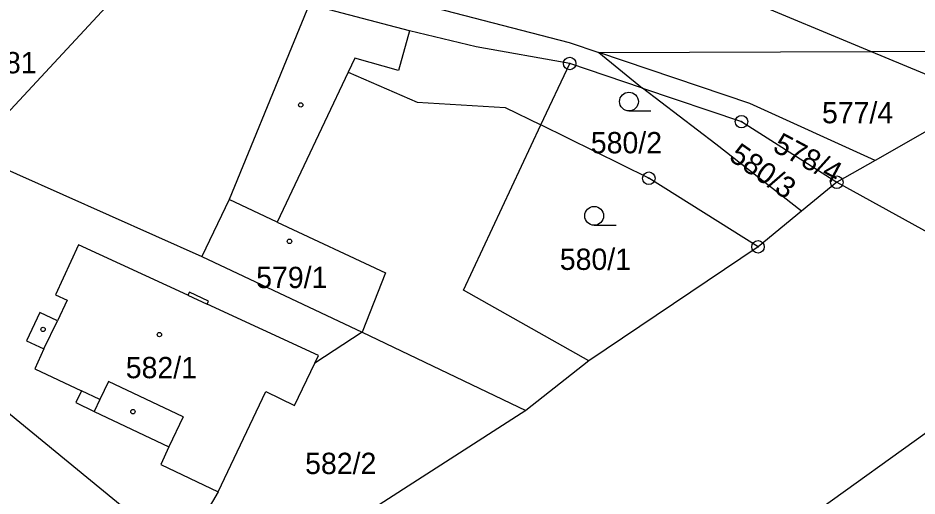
# Model space of a CAD drawing. Extents: x -776606 to -776076, y -974328 to -973875.
# Drawn here: x -776421.1 to -776349.3, y -974258.8 to -974220.6 of the extents above; entities that cross this region are included whole.
import ezdxf

# ---------------------------------------------------------------- set-up
doc = ezdxf.new("R2010")
doc.units = 0
for name, color, linetype in [('Hranice parcel', 7, 'Continuous'), ('Parcelní čísla', 7, 'Continuous'), ('Poz předměty', 7, 'Continuous'), ('Vnitřní kresba', 7, 'Continuous'), ('Značky bodu BP', 7, 'Continuous'), ('Značky budov', 7, 'Continuous'), ('Značky kultur', 7, 'Continuous')]:
    doc.layers.add(name, color=color, linetype=linetype)

msp = doc.modelspace()

# ---------------------------------------------------------------- linework, layer by layer
at = {"layer": 'Hranice parcel'}
for p, q in [((-776374.7, -974223.37), (-776371.21, -974226.22)), ((-776379.34, -974229.15), (-776377.04, -974224.25)), ((-776371.21, -974226.22), (-776377.04, -974224.25)), ((-776370.72, -974233.41), (-776379.34, -974229.15)), ((-776352.62, -974231.99), (-776355.69, -974233.73)), ((-776361.99, -974238.89), (-776370.72, -974233.41)), ((-776355.69, -974233.73), (-776358.51, -974236.04)), ((-776358.51, -974236.04), (-776361.99, -974238.89)), ((-776361.99, -974238.89), (-776375.51, -974247.99)), ((-776406.44, -974239.65), (-776393.62, -974245.71)), ((-776432.18, -974243.72), (-776408.09, -974263.43)), ((-776393.62, -974245.71), (-776397.41, -974248.18)), ((-776393.62, -974245.71), (-776380.54, -974251.96)), ((-776375.51, -974247.99), (-776380.54, -974251.96)), ((-776380.54, -974251.96), (-776403.84, -974266.91)), ((-776405.12, -974258.44), (-776408.09, -974263.43))]:
    msp.add_line(p, q, dxfattribs=at)
for points in [[(-776396.96, -974217.4), (-776377.08, -974222.57), (-776374.7, -974223.37)], [(-776397.85, -974219.54), (-776399.26, -974222.98), (-776404.25, -974235.1), (-776406.44, -974239.65)], [(-776377.04, -974224.25), (-776384.52, -974222.93), (-776389.85, -974221.65), (-776397.85, -974219.54)], [(-776374.7, -974223.37), (-776352.96, -974223.29), (-776340.63, -974223.24)], [(-776352.62, -974231.99), (-776362.64, -974227.45), (-776374.7, -974223.37)], [(-776340.63, -974223.24), (-776343.95, -974227.05), (-776352.62, -974231.99)], [(-776371.21, -974226.22), (-776363.31, -974228.89), (-776355.69, -974233.73)], [(-776358.51, -974236.04), (-776365.36, -974230.68), (-776371.21, -974226.22)], [(-776430.93, -974228.6), (-776424.97, -974231.42), (-776406.44, -974239.65)], [(-776375.51, -974247.99), (-776385.52, -974242.34), (-776379.34, -974229.15)], [(-776397.41, -974248.18), (-776397.12, -974247.56), (-776406, -974243.47), (-776405.89, -974243.22), (-776407.43, -974242.51), (-776407.54, -974242.75), (-776416.28, -974238.73), (-776418.12, -974242.71), (-776417.19, -974243.14), (-776417.97, -974244.8), (-776419.38, -974244.14), (-776420.43, -974246.39), (-776419.05, -974247.04), (-776419.78, -974248.62), (-776416.06, -974250.39), (-776416.51, -974251.32), (-776415.03, -974252.03), (-776409.06, -974254.87), (-776409.72, -974256.26), (-776405.12, -974258.44)], [(-776405.12, -974258.44), (-776401.32, -974250.45), (-776399.02, -974251.55), (-776397.41, -974248.18)]]:
    msp.add_lwpolyline(points, dxfattribs=at)
at = {"layer": 'Poz předměty'}
msp.add_line((-776358.8, -974261.05), (-776342.73, -974249.52), dxfattribs=at)
at = {"layer": 'Vnitřní kresba'}
for p, q in [((-776372.39, -974215.17), (-776352.96, -974223.29)), ((-776424.97, -974231.42), (-776410.75, -974216.12)), ((-776389.85, -974221.65), (-776390.73, -974224.8)), ((-776394.22, -974223.82), (-776394.74, -974224.93)), ((-776390.73, -974224.8), (-776394.22, -974223.82)), ((-776352.96, -974223.29), (-776343.95, -974227.05)), ((-776394.74, -974224.93), (-776400.42, -974236.93)), ((-776394.74, -974224.93), (-776389.22, -974227.33)), ((-776389.22, -974227.33), (-776382.19, -974227.77)), ((-776382.19, -974227.77), (-776379.34, -974229.15)), ((-776355.69, -974233.73), (-776345.5, -974239.35)), ((-776400.42, -974236.93), (-776404.25, -974235.1)), ((-776400.42, -974236.93), (-776391.77, -974240.97)), ((-776391.77, -974240.97), (-776393.62, -974245.71)), ((-776407.54, -974242.75), (-776406, -974243.47)), ((-776419.05, -974247.04), (-776417.97, -974244.8)), ((-776413.9, -974249.65), (-776414.58, -974251.09)), ((-776407.93, -974252.47), (-776413.9, -974249.65)), ((-776414.58, -974251.09), (-776416.06, -974250.39)), ((-776414.58, -974251.09), (-776415.03, -974252.03)), ((-776407.93, -974252.47), (-776409.06, -974254.87))]:
    msp.add_line(p, q, dxfattribs=at)
at = {"layer": 'Značky bodu BP'}
for centre, radius in [((-776377.04, -974224.25), 0.5), ((-776377.04, -974224.25), 0.0303), ((-776363.31, -974228.89), 0.5), ((-776363.31, -974228.89), 0.0303), ((-776370.72, -974233.41), 0.5), ((-776370.72, -974233.41), 0.0303), ((-776355.69, -974233.73), 0.5), ((-776355.69, -974233.73), 0.0303), ((-776361.99, -974238.89), 0.5), ((-776361.99, -974238.89), 0.0303)]:
    msp.add_circle(centre, radius, dxfattribs=at)
at = {"layer": 'Značky budov'}
for centre in [(-776398.527, -974227.559), (-776399.427, -974238.449), (-776419.117, -974245.479), (-776409.827, -974245.899), (-776411.937, -974252.049)]:
    msp.add_circle(centre, 0.175, dxfattribs=at)
at = {"layer": 'Značky kultur'}
for p, q in [((-776372.303, -974228.04), (-776370.553, -974228.04)), ((-776375.083, -974237.16), (-776373.333, -974237.16))]:
    msp.add_line(p, q, dxfattribs=at)
for centre in [(-776372.303, -974227.29), (-776375.083, -974236.41)]:
    msp.add_circle(centre, 0.75, dxfattribs=at)

# ---------------------------------------------------------------- texts
at = {"layer": 'Parcelní čísla'}
for s, p in [('581', (-776423.43, -974225.03)), ('577/4', (-776356.88, -974229.02)), ('580/2', (-776375.35, -974231.42)), ('580/1', (-776377.83, -974240.73)), ('579/1', (-776402.09, -974242.18)), ('582/1', (-776412.51, -974249.38)), ('582/2', (-776398.178, -974257.03))]:
    msp.add_text(s, height=1.7, dxfattribs=at).set_placement(p)
for s, rotation, p in [('578/4', 332, (-776360.909, -974231.2)), ('580/3', 325, (-776364.407, -974231.886))]:
    msp.add_text(s, height=1.7, rotation=rotation, dxfattribs=at).set_placement(p)

doc.saveas('drawing.dxf')
